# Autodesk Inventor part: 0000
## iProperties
Shininess: 64.0
Length Units: 11269
Angle Units: 11279
Time Units: 11290
Mass Units: 11283
Length Display Precision: 3
Angle Display Precision: 2
Compacted: True
Part Number: 0000
Document SubType Name: Sheet Metal
Created: 2004-02
Material: Par défaut
Project: GB000
Designer: Gilles Glemarec
Manufacturer: Standard
Standards Organization: Custom
Density: 0.0
Volumn: 0.0
Area: 0.0
PropertySet Name: Model Information
Control State: 0
Master: False
Checked Out: False
Observations: -
Revision Number: 00
